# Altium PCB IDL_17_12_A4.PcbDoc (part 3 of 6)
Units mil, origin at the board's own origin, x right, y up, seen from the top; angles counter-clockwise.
Board outline 3172.06 x 10350 mil, 6 copper layers (Top Signal, Mid Signal, 3.3 Volt, GND, 5 Volt, Bot Signal), stack 122.8 mil thick; 332 components, 120 nets, 1937 pads, 197 vias.
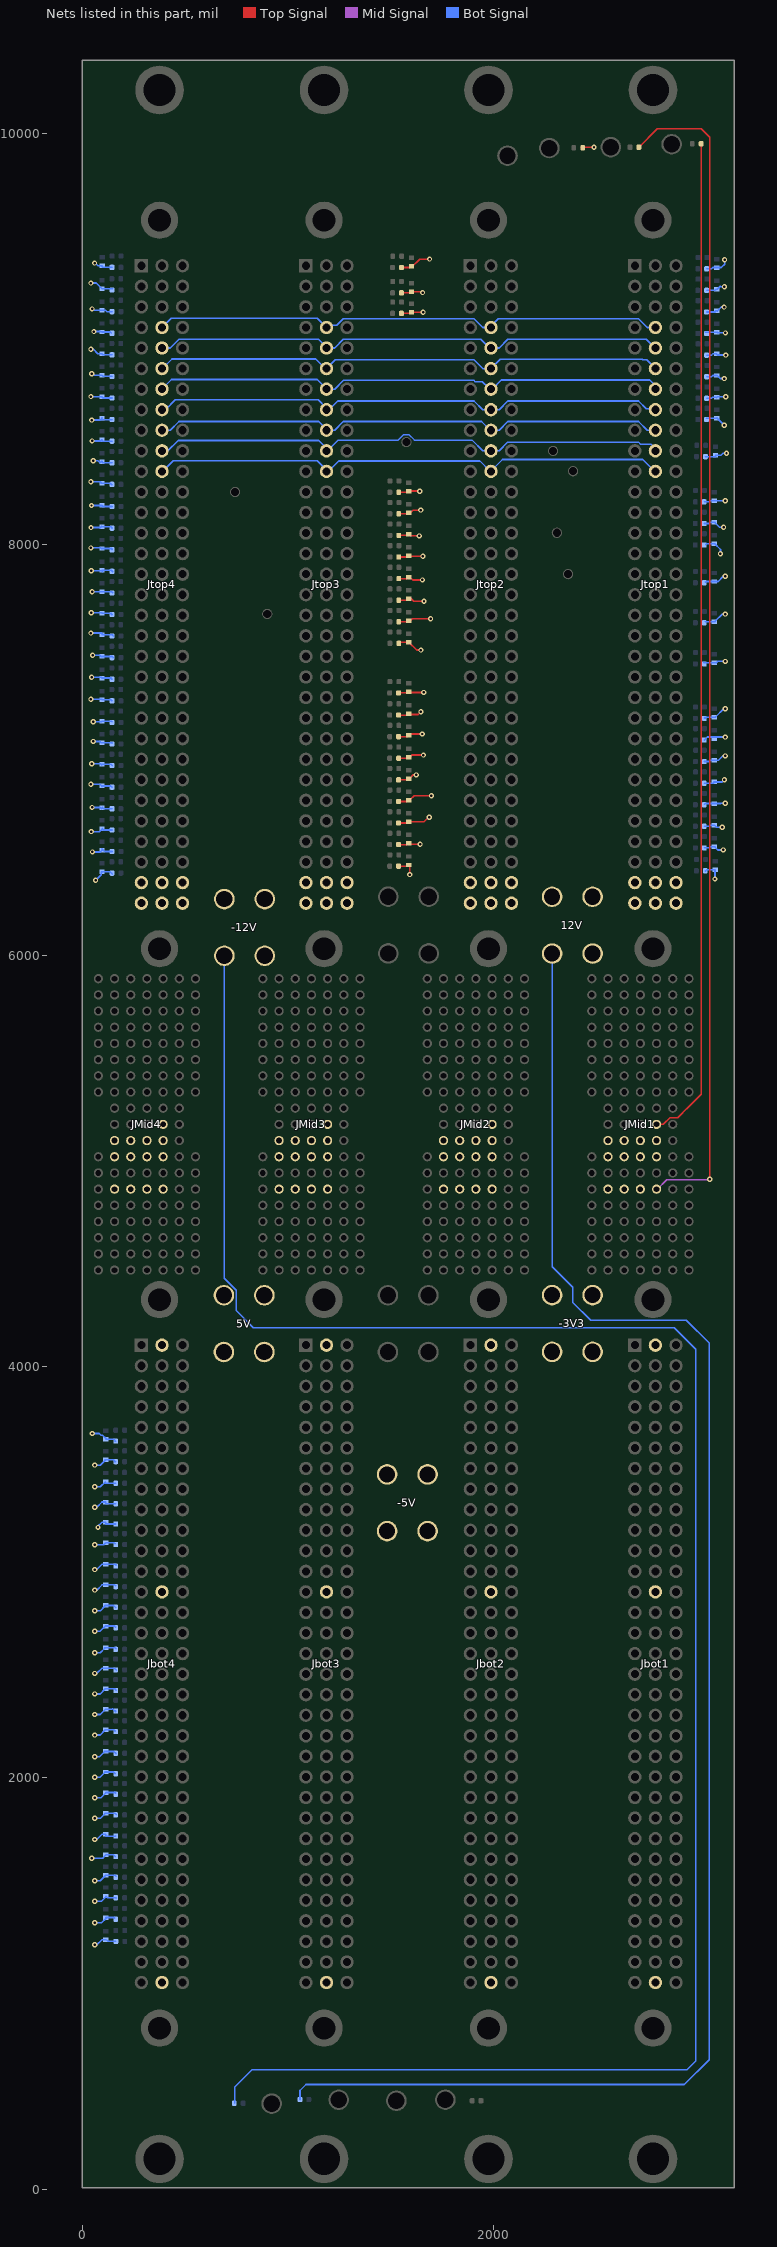
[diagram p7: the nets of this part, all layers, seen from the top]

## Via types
v1: diameter 25.59, hole 12, Top Signal to Bot Signal, 197 vias

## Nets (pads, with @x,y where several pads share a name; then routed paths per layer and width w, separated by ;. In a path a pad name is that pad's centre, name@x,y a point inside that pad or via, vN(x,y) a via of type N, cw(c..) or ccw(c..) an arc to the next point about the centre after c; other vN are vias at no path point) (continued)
5V: 5V.1@689.15,4347.73 5V.2 5V.3 5V.4 CR_IDL_17_12_TerA1.2 CR_IDL_17_12_TerA2.2 CR_IDL_17_12_TerA3.2 CR_IDL_17_12_TerA4.2 CR_IDL_17_12_TerA5.2 CR_IDL_17_12_TerA6.2 CR_IDL_17_12_TerA7.2 CR_IDL_17_12_TerA8.2 CR_IDL_17_12_TerA9.2 CR_IDL_17_12_TerA10.2 CR_IDL_17_12_TerA11.2 CR_IDL_17_12_TerA12.2 CR_IDL_17_12_TerA13.2 CR_IDL_17_12_TerA14.2 CR_IDL_17_12_TerA15.2 CR_IDL_17_12_TerA16.2 CR_IDL_17_12_TerA17.2 CR_IDL_17_12_TerA18.2 CR_IDL_17_12_TerA19.2 CR_IDL_17_12_TerA20.2 CR_IDL_17_12_TerA21.2 CR_IDL_17_12_TerA22.2 CR_IDL_17_12_TerA23.2 CR_IDL_17_12_TerA24.2 CR_IDL_17_12_TerA25.2 CR_IDL_17_12_TerA26.2 CR_IDL_17_12_TerA27.2 CR_IDL_17_12_TerA28.2 CR_IDL_17_12_TerA29.2 CR_IDL_17_12_TerA30.2 CR_IDL_17_12_TerA31.2 CR_IDL_17_12_TerA32.2 CR_IDL_17_12_TerA33.2 CR_IDL_17_12_TerA34.2 CR_IDL_17_12_TerA35.2 CR_IDL_17_12_TerA36.2 CR_IDL_17_12_TerA37.2 CR_IDL_17_12_TerA38.2 CR_IDL_17_12_TerA39.2 CR_IDL_17_12_TerA40.2 CR_IDL_17_12_TerA41.2 CR_IDL_17_12_TerA42.2 CR_IDL_17_12_TerA43.2 CR_IDL_17_12_TerA44.2 CR_IDL_17_12_TerA45.2 CR_IDL_17_12_TerA46.2 CR_IDL_17_12_TerA47.2 CR_IDL_17_12_TerA48.2 CR_IDL_17_12_TerA49.2 CR_IDL_17_12_TerA50.2 CR_IDL_17_12_TerA51.2 CR_IDL_17_12_TerA52.2 CR_IDL_17_12_TerA53.2 CR_IDL_17_12_TerA54.2 CR_IDL_17_12_TerA55.2 CR_IDL_17_12_TerA56.2 CR_IDL_17_12_TerA57.2 CR_IDL_17_12_TerA58.2 CR_IDL_17_12_TerA59.2 CR_IDL_17_12_TerA60.2 CR_IDL_17_12_TerA61.2 CR_IDL_17_12_TerA62.2 CR_IDL_17_12_TerA63.2 CR_IDL_17_12_TerA64.2 CR_IDL_17_12_TerA65.2 CR_IDL_17_12_TerA66.2 CR_IDL_17_12_TerA67.2 CR_IDL_17_12_TerA68.2 CR_IDL_17_12_TerA69.2 CR_IDL_17_12_TerA70.2 CR_IDL_17_12_TerA71.2 CR_IDL_17_12_TerA72.2 CRB_IDL_17_12_TerB1.2 CRB_IDL_17_12_TerB2.2 CRB_IDL_17_12_TerB3.2 CRB_IDL_17_12_TerB4.2 CRB_IDL_17_12_TerB5.2 CRB_IDL_17_12_TerB6.2 CRB_IDL_17_12_TerB7.2 CRB_IDL_17_12_TerB8.2 CRB_IDL_17_12_TerB9.2 CRB_IDL_17_12_TerB10.2 CRB_IDL_17_12_TerB11.2 CRB_IDL_17_12_TerB12.2 CRB_IDL_17_12_TerB13.2 CRB_IDL_17_12_TerB14.2 CRB_IDL_17_12_TerB15.2 CRB_IDL_17_12_TerB16.2 CRB_IDL_17_12_TerB17.2 CRB_IDL_17_12_TerB18.2 CRB_IDL_17_12_TerB19.2 CRB_IDL_17_12_TerB20.2 CRB_IDL_17_12_TerB21.2 CRB_IDL_17_12_TerB22.2 CRB_IDL_17_12_TerB23.2 CRB_IDL_17_12_TerB24.2 CRB_IDL_17_12_TerB25.2 Jbot1.B1 Jbot1.B13 Jbot1.B32 Jbot2.B1 Jbot2.B13 Jbot2.B32 Jbot3.B1 Jbot3.B13 Jbot3.B32 Jbot4.B1 Jbot4.B13 Jbot4.B32 Jtop1.A32 Jtop1.B31 Jtop1.B32 Jtop1.C32 Jtop2.A32 Jtop2.B31 Jtop2.B32 Jtop2.C32 Jtop3.A32 Jtop3.B31 Jtop3.B32 Jtop3.C32 Jtop4.A32 Jtop4.B31 Jtop4.B32 Jtop4.C32 R1R_IDL_17_12_TerA1.2 R1R_IDL_17_12_TerA2.2 R1R_IDL_17_12_TerA3.2 R1R_IDL_17_12_TerA4.2 R1R_IDL_17_12_TerA5.2 R1R_IDL_17_12_TerA6.2 R1R_IDL_17_12_TerA7.2 R1R_IDL_17_12_TerA8.2 R1R_IDL_17_12_TerA9.2 R1R_IDL_17_12_TerA10.2 R1R_IDL_17_12_TerA11.2 R1R_IDL_17_12_TerA12.2 R1R_IDL_17_12_TerA13.2 R1R_IDL_17_12_TerA14.2 R1R_IDL_17_12_TerA15.2 R1R_IDL_17_12_TerA16.2 R1R_IDL_17_12_TerA17.2 R1R_IDL_17_12_TerA18.2 R1R_IDL_17_12_TerA19.2 R1R_IDL_17_12_TerA20.2 R1R_IDL_17_12_TerA21.2 R1R_IDL_17_12_TerA22.2 R1R_IDL_17_12_TerA23.2 R1R_IDL_17_12_TerA24.2 R1R_IDL_17_12_TerA25.2 R1R_IDL_17_12_TerA26.2 R1R_IDL_17_12_TerA27.2 R1R_IDL_17_12_TerA28.2 R1R_IDL_17_12_TerA29.2 R1R_IDL_17_12_TerA30.2 R1R_IDL_17_12_TerA31.2 R1R_IDL_17_12_TerA32.2 R1R_IDL_17_12_TerA33.2 R1R_IDL_17_12_TerA34.2 R1R_IDL_17_12_TerA35.2 R1R_IDL_17_12_TerA36.2 R1R_IDL_17_12_TerA37.2 R1R_IDL_17_12_TerA38.2 R1R_IDL_17_12_TerA39.2 R1R_IDL_17_12_TerA40.2 R1R_IDL_17_12_TerA41.2 R1R_IDL_17_12_TerA42.2 R1R_IDL_17_12_TerA43.2 R1R_IDL_17_12_TerA44.2 R1R_IDL_17_12_TerA45.2 R1R_IDL_17_12_TerA46.2 R1R_IDL_17_12_TerA47.2 R1R_IDL_17_12_TerA48.2 R1R_IDL_17_12_TerA49.2 R1R_IDL_17_12_TerA50.2 R1R_IDL_17_12_TerA51.2 R1R_IDL_17_12_TerA52.2 R1R_IDL_17_12_TerA53.2 R1R_IDL_17_12_TerA54.2 R1R_IDL_17_12_TerA55.2 R1R_IDL_17_12_TerA56.2 R1R_IDL_17_12_TerA57.2 R1R_IDL_17_12_TerA58.2 R1R_IDL_17_12_TerA59.2 R1R_IDL_17_12_TerA60.2 R1R_IDL_17_12_TerA61.2 R1R_IDL_17_12_TerA62.2 R1R_IDL_17_12_TerA63.2 R1R_IDL_17_12_TerA64.2 R1R_IDL_17_12_TerA65.2 R1R_IDL_17_12_TerA66.2 R1R_IDL_17_12_TerA67.2 R1R_IDL_17_12_TerA68.2 R1R_IDL_17_12_TerA69.2 R1R_IDL_17_12_TerA70.2 R1R_IDL_17_12_TerA71.2 R1R_IDL_17_12_TerA72.2 R1RB_IDL_17_12_TerB1.2 R1RB_IDL_17_12_TerB2.2 R1RB_IDL_17_12_TerB3.2 R1RB_IDL_17_12_TerB4.2 R1RB_IDL_17_12_TerB5.2 R1RB_IDL_17_12_TerB6.2 R1RB_IDL_17_12_TerB7.2 R1RB_IDL_17_12_TerB8.2 R1RB_IDL_17_12_TerB9.2 R1RB_IDL_17_12_TerB10.2 R1RB_IDL_17_12_TerB11.2 R1RB_IDL_17_12_TerB12.2 R1RB_IDL_17_12_TerB13.2 R1RB_IDL_17_12_TerB14.2 R1RB_IDL_17_12_TerB15.2 R1RB_IDL_17_12_TerB16.2 R1RB_IDL_17_12_TerB17.2 R1RB_IDL_17_12_TerB18.2 R1RB_IDL_17_12_TerB19.2 R1RB_IDL_17_12_TerB20.2 R1RB_IDL_17_12_TerB21.2 R1RB_IDL_17_12_TerB22.2 R1RB_IDL_17_12_TerB23.2 R1RB_IDL_17_12_TerB24.2 R1RB_IDL_17_12_TerB25.2 R5.2 | length 10859.5
  Top Signal w8: R1R_IDL_17_12_TerA24.2@1538.9,6434.64 1583.44,6434.64 1588.6,6439.8 CR_IDL_17_12_TerA24.2@1592.4,6443.59 ; R1R_IDL_17_12_TerA25.2@1538.9,6539.64 1579.21,6539.64 CR_IDL_17_12_TerA25.2@1586.42,6546.84 ; R1R_IDL_17_12_TerA26.2@1538.9,6644.64 1580.88,6644.64 CR_IDL_17_12_TerA26.2@1587.32,6651.08 ; R1R_IDL_17_12_TerA27.2@1538.9,6749.64 1577.14,6749.64 1585.45,6757.95 CR_IDL_17_12_TerA27.2@1586.49,6758.99 ; R1R_IDL_17_12_TerA28.2@1538.9,6854.64 1577.83,6854.64 CR_IDL_17_12_TerA28.2@1585.51,6862.31 ; R1R_IDL_17_12_TerA29.2@1538.9,6959.64 1579.01,6959.64 CR_IDL_17_12_TerA29.2@1584.53,6965.15 ; R1R_IDL_17_12_TerA30.2@1538.9,7064.64 1581.18,7064.64 CR_IDL_17_12_TerA30.2@1582.86,7066.32 ; R1R_IDL_17_12_TerA31.2@1538.9,7169.64 1584.33,7169.64 CR_IDL_17_12_TerA31.2@1588.95,7174.26 ; R1R_IDL_17_12_TerA32.2@1538.9,7277.64 1577.03,7277.64 1585.4,7286.01 CR_IDL_17_12_TerA32.2@1585.98,7286.59 ; R1R_IDL_17_12_TerA33.2@1539.86,7518.53 1545.3,7523.98 CR_IDL_17_12_TerA33.2@1588.79,7523.98 ; R1R_IDL_17_12_TerA34.2@1539.86,7623.53 1582.98,7623.53 1588.85,7629.4 CR_IDL_17_12_TerA34.2@1592.32,7632.87 ; R1R_IDL_17_12_TerA35.2@1539.86,7728.53 1579.98,7728.53 1587.35,7735.9 CR_IDL_17_12_TerA35.2@1587.85,7736.4 ; R1R_IDL_17_12_TerA36.2@1539.86,7833.53 1581.44,7833.53 CR_IDL_17_12_TerA36.2@1587.85,7839.94 ; R1R_IDL_17_12_TerA37.2@1539.86,7938.53 1585.58,7938.53 CR_IDL_17_12_TerA37.2@1587.85,7940.8 ; R1R_IDL_17_12_TerA38.2@1539.86,8043.53 1580.8,8043.53 CR_IDL_17_12_TerA38.2@1586.07,8048.8 ; R1R_IDL_17_12_TerA39.2@1539.86,8148.53 1587.62,8148.53 1591.17,8152.08 CR_IDL_17_12_TerA39.2@1592.32,8153.23 ; R1R_IDL_17_12_TerA40.2@1539.86,8253.53 1588.19,8253.53 1591.45,8256.8 CR_IDL_17_12_TerA40.2@1593.21,8258.55 ; R1R_IDL_17_12_TerA43.2@1552.83,9346.47 1593.74,9346.47 CR_IDL_17_12_TerA43.2@1600.3,9353.03 ; R1R_IDL_17_12_TerA41.2@1552.9,9123.5 1599.94,9123.5 CR_IDL_17_12_TerA41.2@1603.07,9126.63 ; R1R_IDL_17_12_TerA42.2@1552.9,9223.5 1594.16,9223.5 1600.96,9230.3 CR_IDL_17_12_TerA42.2@1601.38,9230.72 ; CR_IDL_17_12_TerA30.2@1582.88,7066.3 1587.49,7070.91 1594.14,7077.56 v1(1654.34,7077.56) ; CR_IDL_17_12_TerA29.2@1587.18,6962.58 CR_IDL_17_12_TerA29.2@1589,6964.4 ; CR_IDL_17_12_TerA26.2@1587.86,6650.54 1662.88,6650.54 v1@1686.23,6673.9 ; CR_IDL_17_12_TerA33.2@1588.79,7524.33 1627.16,7485.96 v1(1647.64,7485.96) ; CR_IDL_17_12_TerA40.2@1588.81,8259.44 1642.33,8259.44 1643.18,8259.44 v1@1645.87,8262.12 ; CR_IDL_17_12_TerA29.2@1589.52,6960.85 1591.04,6962.36 1604.9,6976.22 1605.75,6975.36 v1(1659.66,6975.36) ; CR_IDL_17_12_TerA25.2@1589.84,6543.42 1592.23,6541.03 v1(1643.44,6541.03) ; CR_IDL_17_12_TerA24.2@1590.64,6439.47 1592.97,6437.14 v1(1592.97,6394.12) ; CR_IDL_17_12_TerA31.2@1591.1,7172.76 1635.32,7172.76 v1(1647.85,7185.29) ; CR_IDL_17_12_TerA38.2@1591.81,8044.65 1595.25,8041.21 v1(1639.76,8041.21) ; CR_IDL_17_12_TerA32.2@1593.84,7281.96 1596.18,7279.61 v1(1660.76,7279.61) ; CR_IDL_17_12_TerA28.2@1594.23,6862.39 1610.57,6878.73 v1(1625.38,6878.73) ; CR_IDL_17_12_TerA37.2@1594.89,7943.26 1595.47,7942.68 v1(1657.31,7942.68) ; CR_IDL_17_12_TerA39.2@1595.28,8152.99 1608.95,8166.66 v1(1647.17,8166.66) ; CR_IDL_17_12_TerA27.2@1595.79,6759.06 1614.62,6777.88 v1(1698.8,6777.88) ; CR_IDL_17_12_TerA35.2@1596.63,7739.75 1612.9,7723.48 v1(1662.58,7723.48) ; CR_IDL_17_12_TerA36.2@1596.97,7837.36 1607.52,7826.81 v1(1655.14,7826.81) ; CR_IDL_17_12_TerA34.2@1598.09,7630.59 1605.85,7638.35 1606.62,7637.58 v1(1694.69,7637.58) ; CR_IDL_17_12_TerA41.2@1601.86,9129.41 v1(1658.08,9129.39) 1658.31,9129.41 v1@1658.71,9129.81 ; CR_IDL_17_12_TerA42.2@1601.86,9229.41 1651.8,9229.41 v1@1655.52,9225.69 ; CR_IDL_17_12_TerA43.2@1604.05,9349.28 1604.46,9349.7 1642.18,9387.42 v1(1689.41,9387.42) ; v1@1686.23,6672.65 v1(1687.49,6672.65) ; R5.2@2427.91,9929.8 2428.82,9930.71 2434.51,9930.71 v1@2484.35,9930.71
  Bot Signal w8: v1@41.67,9270.96 42.59,9270.96 68.02,9270.96 CR_IDL_17_12_TerA71.2@96.11,9242.87 145.07,9242.87 147.59,9242.87 R1R_IDL_17_12_TerA71.2@147.8,9243.08 ; v1(42.59,6832.73) 86.8,6832.73 CR_IDL_17_12_TerA48.2@94.66,6824.87 ; v1(42.59,7246.73) CR_IDL_17_12_TerA52.2@96.11,7246.73 ; v1(42.59,7568.73) 95.01,7568.73 99.99,7563.76 CR_IDL_17_12_TerA55.2@100.42,7563.32 ; v1(42.59,7982.73) 89.51,7982.73 CR_IDL_17_12_TerA59.2@92.37,7979.87 ; v1(42.59,8304.73) 87.39,8304.73 CR_IDL_17_12_TerA62.2@91.26,8300.86 ; v1(42.59,8718.73) 64.68,8718.73 65.53,8717.87 CR_IDL_17_12_TerA66.2@96.11,8717.87 ; v1(42.59,8948.73) 54.68,8948.73 75.53,8927.87 CR_IDL_17_12_TerA68.2@96.11,8927.87 ; v1(42.87,8081.94) 89.32,8081.94 CR_IDL_17_12_TerA60.2@92.25,8084.87 ; v1(43.55,7667.69) 95.54,7667.69 97.23,7666 CR_IDL_17_12_TerA56.2@98.36,7664.87 ; v1(43.88,7871.42) 95.89,7871.42 CR_IDL_17_12_TerA58.2@99.07,7868.25 ; v1(44.02,6602.94) 83.46,6602.94 84.59,6601.81 97.88,6615.1 CR_IDL_17_12_TerA46.2@98.23,6615.45 ; v1(45.27,8189.08) 87.92,8189.08 CR_IDL_17_12_TerA61.2@90.58,8186.43 ; v1(45.52,7353.76) 93.68,7353.76 CR_IDL_17_12_TerA53.2@96.84,7350.6 ; v1(45.96,8604.68) 87.42,8604.68 CR_IDL_17_12_TerA65.2@91.42,8608.68 ; v1(46.66,8829.91) 46.66,8834.92 49.17,8832.41 58.71,8822.87 CR_IDL_17_12_TerA67.2@96.11,8822.87 CR_IDL_17_12_TerA67.2@98.39,8822.87 ; v1(46.72,1609.92) 100.27,1609.92 CRB_IDL_17_12_TerB5.2@111.44,1621.09 ; v1(47.01,6933.26) 89.04,6933.26 CR_IDL_17_12_TerA49.2@92.42,6929.87 ; v1(47.86,7769.72) CR_IDL_17_12_TerA57.2@91.74,7769.72 ; v1(48.05,8502.87) 88.84,8502.87 CR_IDL_17_12_TerA64.2@92.44,8506.47 ; v1(48.05,9145.09) 48.05,9148.53 49.77,9146.81 58.71,9137.87 CR_IDL_17_12_TerA70.2@96.11,9137.87 115.37,9137.87 121.28,9131.97 R1R_IDL_17_12_TerA70.2@145.07,9131.97 ; v1(48.19,6720.46) 88.75,6720.46 92.72,6716.49 CR_IDL_17_12_TerA47.2@94.44,6714.77 ; v1(48.7,3675.32) 83.78,3675.32 91.65,3667.45 99.25,3667.45 117.1,3649.6 CRB_IDL_17_12_TerB25.2@118.61,3648.09 ; v1(49.73,6503.82) 87.85,6503.82 CR_IDL_17_12_TerA45.2@94.24,6510.21 ; v1(50.5,7461.27) 86.36,7461.27 CR_IDL_17_12_TerA54.2@90.46,7457.17 ; v1(53.84,8406.95) 77.41,8406.95 86.78,8397.58 CR_IDL_17_12_TerA63.2@92.07,8402.87 ; v1(54.26,7041.27) 86.39,7041.27 CR_IDL_17_12_TerA50.2@92.53,7035.14 ; v1@54.48,7136.82 93.05,7136.82 CR_IDL_17_12_TerA51.2@96.11,7139.87 142.53,7139.87 R1R_IDL_17_12_TerA51.2@145.25,7137.16 ; v1(57.32,9035.23) 91.07,9035.23 CR_IDL_17_12_TerA69.2@91.56,9034.74 ; v1(60.92,1295.61) 93.84,1295.61 CRB_IDL_17_12_TerB2.2@116.46,1318.22 ; v1(60.92,1400.61) 93.76,1400.61 CRB_IDL_17_12_TerB3.2@114.45,1421.3 ; v1(60.92,1500.61) 88.34,1500.61 CRB_IDL_17_12_TerB4.2@112.78,1525.05 ; v1(60.92,1700.61) 70.78,1700.61 96.11,1725.94 CRB_IDL_17_12_TerB6.2@114.44,1725.94 114.44,1717.03 163.26,1717.03 R1RB_IDL_17_12_TerB6.2@163.26,1717.44 ; v1(60.92,1803.61) 89.14,1803.61 CRB_IDL_17_12_TerB7.2@111.1,1825.57 ; v1(60.92,1903.61) 91.18,1903.61 115.48,1927.91 CRB_IDL_17_12_TerB8.2@116.51,1928.94 ; v1(60.92,2003.61) 86.88,2003.61 CRB_IDL_17_12_TerB9.2@110.86,2027.59 ; v1(60.92,2103.61) 84.62,2103.61 CRB_IDL_17_12_TerB10.2@108.68,2127.67 ; v1(60.92,2208.61) 87.46,2208.61 CRB_IDL_17_12_TerB11.2@110.49,2231.64 ; v1(60.92,2308.61) 88.57,2308.61 CRB_IDL_17_12_TerB12.2@112.66,2332.7 ; v1(60.92,2408.61) 87.5,2408.61 CRB_IDL_17_12_TerB13.2@112.66,2433.77 ; v1(60.92,2508.61) 70.78,2508.61 96.11,2533.94 CRB_IDL_17_12_TerB14.2@114.44,2533.94 156.67,2533.94 164.22,2526.39 R1RB_IDL_17_12_TerB14.2@165.91,2524.7 ; v1(60.92,2608.61) 87.54,2608.61 CRB_IDL_17_12_TerB15.2@108.31,2629.39 ; v1(60.92,2713.61) 86.96,2713.61 CRB_IDL_17_12_TerB16.2@111.6,2738.25 ; v1(60.92,2813.61) 89.04,2813.61 CRB_IDL_17_12_TerB17.2@110.1,2834.67 ; v1(60.92,2913.61) 70.78,2913.61 96.11,2938.94 CRB_IDL_17_12_TerB18.2@114.44,2938.94 158.66,2938.94 R1RB_IDL_17_12_TerB18.2@163.33,2934.26 ; v1(60.92,3013.61) 70.78,3013.61 96.11,3038.94 CRB_IDL_17_12_TerB19.2@114.44,3038.94 160.71,3038.94 R1RB_IDL_17_12_TerB19.2@165.59,3034.06 ; v1(60.92,3134.61) 105.49,3134.61 CRB_IDL_17_12_TerB20.2@111.82,3140.94 ; v1(60.92,3316.61) 70.78,3316.61 96.11,3341.94 CRB_IDL_17_12_TerB22.2@114.44,3341.94 114.44,3333.03 163.26,3333.03 R1RB_IDL_17_12_TerB22.2@163.26,3333.44 ; v1(60.92,3416.61) 88.42,3416.61 CRB_IDL_17_12_TerB23.2@111.5,3439.69 ; v1(60.92,3521.61) 87.78,3521.61 CRB_IDL_17_12_TerB24.2@111.93,3545.76 ; v1(61.62,1188.14) 71.47,1188.14 96.8,1213.47 CRB_IDL_17_12_TerB1.2@115.14,1213.47 ; v1@62.22,9369.75 76.63,9355.34 CR_IDL_17_12_TerA72.2@97.42,9355.34 ; v1(65.37,6365.68) 89.73,6390.05 92.13,6390.05 CR_IDL_17_12_TerA44.2@92.13,6403.15 ; 76.53,8189.87 CR_IDL_17_12_TerA61.2@96.11,8189.87 ; v1(76.92,3218.61) 70.78,3218.61 73.85,3221.68 96.11,3243.94 CRB_IDL_17_12_TerB21.2@114.44,3243.94 114.44,3235.03 163.26,3235.03 R1RB_IDL_17_12_TerB21.2@163.26,3235.44 ; CR_IDL_17_12_TerA54.2@90.46,7454.87 CR_IDL_17_12_TerA54.2@96.11,7454.87 145.03,7454.87 148,7451.9 R1R_IDL_17_12_TerA54.2@151.36,7448.55 ; CR_IDL_17_12_TerA62.2@91.26,8297.87 CR_IDL_17_12_TerA62.2@96.11,8297.87 136.35,8297.87 143.66,8290.56 R1R_IDL_17_12_TerA62.2@144.91,8289.32 ; CR_IDL_17_12_TerA57.2@92.07,7769.87 CR_IDL_17_12_TerA57.2@96.11,7769.87 143.11,7769.87 147.04,7765.94 R1R_IDL_17_12_TerA57.2@148.3,7764.68 ; CR_IDL_17_12_TerA57.2@92.07,7770.04 CR_IDL_17_12_TerA57.2@91.74,7769.72 ; CR_IDL_17_12_TerA44.2@92.13,6406.56 CR_IDL_17_12_TerA44.2@92.13,6403.15 ; CR_IDL_17_12_TerA57.2@93.29,7769.44 93.01,7769.72 CR_IDL_17_12_TerA57.2@91.74,7769.72 ; CR_IDL_17_12_TerA72.2@93.55,9354.51 95.07,9352.99 100.54,9347.52 R1R_IDL_17_12_TerA72.2@145.05,9347.52 ; CR_IDL_17_12_TerA64.2@93.85,8507.87 CR_IDL_17_12_TerA64.2@96.11,8507.87 ; CR_IDL_17_12_TerA64.2@93.97,8504.94 96.95,8501.97 R1R_IDL_17_12_TerA64.2@145.07,8501.97 ; CR_IDL_17_12_TerA59.2@94.31,7977.93 94.24,7978.01 CR_IDL_17_12_TerA59.2@92.37,7979.87 ; CR_IDL_17_12_TerA63.2@94.31,8405.11 94.09,8404.89 CR_IDL_17_12_TerA63.2@92.07,8402.87 ; CR_IDL_17_12_TerA44.2@94.57,6405.59 CR_IDL_17_12_TerA44.2@92.13,6403.15 ; CR_IDL_17_12_TerA60.2@94.65,8087.27 94.18,8086.8 CR_IDL_17_12_TerA60.2@92.25,8084.87 ; CR_IDL_17_12_TerA45.2@94.71,6519.95 99.44,6515.21 108.69,6505.97 R1R_IDL_17_12_TerA45.2@145.07,6505.97 ; CR_IDL_17_12_TerA49.2@95.33,6926.97 94.26,6928.03 CR_IDL_17_12_TerA49.2@92.42,6929.87 ; CR_IDL_17_12_TerA61.2@95.33,8186.77 98.13,8183.97 R1R_IDL_17_12_TerA61.2@145.07,8183.97 ; CR_IDL_17_12_TerA44.2@95.41,6406.87 CR_IDL_17_12_TerA44.2@96.11,6406.87 136.8,6406.87 143.89,6399.79 R1R_IDL_17_12_TerA44.2@146.94,6396.74 ; CR_IDL_17_12_TerA50.2@96.11,7034.87 145.07,7034.87 145.32,7034.87 R1R_IDL_17_12_TerA50.2@146.94,7033.25 ; CR_IDL_17_12_TerA52.2@96.11,7244.87 139.06,7244.87 R1R_IDL_17_12_TerA52.2@140.83,7243.11 ; CR_IDL_17_12_TerA53.2@96.11,7349.87 140.69,7349.87 R1R_IDL_17_12_TerA53.2@142.53,7348.03 ; CR_IDL_17_12_TerA55.2@96.11,7559.87 145.07,7559.87 145.98,7559.87 148.47,7557.38 R1R_IDL_17_12_TerA55.2@151.36,7554.49 ; CR_IDL_17_12_TerA56.2@96.11,7664.87 CR_IDL_17_12_TerA56.2@98.36,7664.87 ; CR_IDL_17_12_TerA58.2@96.11,7874.87 140.66,7874.87 145.82,7869.72 R1R_IDL_17_12_TerA58.2@148.3,7867.23 ; CR_IDL_17_12_TerA63.2@96.11,8402.87 CR_IDL_17_12_TerA63.2@92.07,8402.87 ; CR_IDL_17_12_TerA69.2@96.11,9032.87 136.49,9032.87 R1R_IDL_17_12_TerA69.2@141.35,9028.02 ; CR_IDL_17_12_TerA46.2@97.21,6617.98 CR_IDL_17_12_TerA46.2@100.13,6615.07 ; CR_IDL_17_12_TerA63.2@97.37,8399.68 100.08,8396.97 R1R_IDL_17_12_TerA63.2@145.07,8396.97 ; CR_IDL_17_12_TerA65.2@98.05,8615.3 95.86,8613.12 CR_IDL_17_12_TerA65.2@91.42,8608.68 ; CR_IDL_17_12_TerA48.2@98.23,6821.3 95.38,6824.15 CR_IDL_17_12_TerA48.2@94.66,6824.87 ; CR_IDL_17_12_TerA66.2@98.39,8713.44 99.86,8711.97 R1R_IDL_17_12_TerA66.2@145.07,8711.97 ; CR_IDL_17_12_TerA67.2@98.39,8821.08 102.5,8816.97 R1R_IDL_17_12_TerA67.2@145.07,8816.97 ; CR_IDL_17_12_TerA68.2@98.61,8923.78 100.42,8921.97 R1R_IDL_17_12_TerA68.2@145.07,8921.97 ; CR_IDL_17_12_TerA47.2@98.73,6720.15 104.91,6713.97 R1R_IDL_17_12_TerA47.2@145.07,6713.97 ; CR_IDL_17_12_TerA46.2@100.13,6610.97 R1R_IDL_17_12_TerA46.2@145.07,6610.97 ; CRB_IDL_17_12_TerB15.2@108.31,2633.94 CRB_IDL_17_12_TerB15.2@114.44,2633.94 158.1,2633.94 R1RB_IDL_17_12_TerB15.2@164.46,2627.58 ; CRB_IDL_17_12_TerB10.2@108.68,2128.94 CRB_IDL_17_12_TerB10.2@114.44,2128.94 153.77,2128.94 162.77,2119.95 R1RB_IDL_17_12_TerB10.2@164.46,2118.25 ; CRB_IDL_17_12_TerB17.2@110.1,2838.94 CRB_IDL_17_12_TerB17.2@114.44,2838.94 152.79,2838.94 162.28,2829.45 R1RB_IDL_17_12_TerB17.2@162.56,2829.17 ; CRB_IDL_17_12_TerB11.2@110.49,2233.94 CRB_IDL_17_12_TerB11.2@114.44,2233.94 154.91,2233.94 R1RB_IDL_17_12_TerB11.2@161.2,2227.65 ; CRB_IDL_17_12_TerB9.2@110.86,2028.94 CRB_IDL_17_12_TerB9.2@114.44,2028.94 153.09,2028.94 R1RB_IDL_17_12_TerB9.2@160.87,2021.16 ; CRB_IDL_17_12_TerB7.2@111.1,1828.94 CRB_IDL_17_12_TerB7.2@114.44,1828.94 158.6,1828.94 165.18,1822.36 R1RB_IDL_17_12_TerB7.2@165.32,1822.22 ; CRB_IDL_17_12_TerB24.2@111.24,3546.94 CRB_IDL_17_12_TerB24.2@114.44,3546.94 153.78,3546.94 R1RB_IDL_17_12_TerB24.2@157.42,3543.31 ; CRB_IDL_17_12_TerB23.2@111.5,3436.15 114.22,3433.44 114.44,3433.44 R1RB_IDL_17_12_TerB23.2@163.26,3433.44 ; CRB_IDL_17_12_TerB16.2@111.6,2738.94 CRB_IDL_17_12_TerB16.2@114.44,2738.94 156.87,2738.94 R1RB_IDL_17_12_TerB16.2@163.06,2732.75 ; CRB_IDL_17_12_TerB12.2@112.66,2333.94 CRB_IDL_17_12_TerB12.2@114.44,2333.94 143.6,2333.94 147.07,2337.42 R1RB_IDL_17_12_TerB12.2@159.05,2325.44 ; CRB_IDL_17_12_TerB13.2@112.66,2433.94 CRB_IDL_17_12_TerB13.2@114.44,2433.94 158.13,2433.94 164.95,2427.13 R1RB_IDL_17_12_TerB13.2@165.19,2426.89 ; CRB_IDL_17_12_TerB4.2@112.78,1525.94 CRB_IDL_17_12_TerB4.2@114.44,1525.94 160.07,1525.94 R1RB_IDL_17_12_TerB4.2@164.32,1521.7 ; CRB_IDL_17_12_TerB2.2@114.44,1320.94 155.24,1320.94 R1RB_IDL_17_12_TerB2.2@157.29,1318.89 ; CRB_IDL_17_12_TerB5.2@114.44,1625.94 152.44,1625.94 R1RB_IDL_17_12_TerB5.2@160.63,1617.75 ; CRB_IDL_17_12_TerB8.2@114.44,1928.94 CRB_IDL_17_12_TerB8.2@116.51,1928.94 ; CRB_IDL_17_12_TerB20.2@114.44,3143.94 155.18,3143.94 R1RB_IDL_17_12_TerB20.2@160.44,3138.69 ; CRB_IDL_17_12_TerB25.2@114.44,3646.94 155.15,3646.94 R1RB_IDL_17_12_TerB25.2@159.24,3642.85 ; CRB_IDL_17_12_TerB3.2@116.14,1424.77 123.48,1417.44 R1RB_IDL_17_12_TerB3.2@163.16,1417.44 ; CRB_IDL_17_12_TerB1.2@118.73,1213.31 127.08,1204.96 R1RB_IDL_17_12_TerB1.2@163.95,1204.96 ; R1R_IDL_17_12_TerA52.2@140.83,7238.97 R1R_IDL_17_12_TerA52.2@145.07,7238.97 ; R1R_IDL_17_12_TerA56.2@141.85,7658.97 R1R_IDL_17_12_TerA56.2@145.07,7658.97 ; R1R_IDL_17_12_TerA56.2@141.85,7664.51 141.49,7664.87 CR_IDL_17_12_TerA56.2@98.36,7664.87 ; R1R_IDL_17_12_TerA53.2@142.53,7343.97 R1R_IDL_17_12_TerA53.2@145.07,7343.97 ; R1R_IDL_17_12_TerA59.2@144.91,7973.97 R1R_IDL_17_12_TerA59.2@145.07,7973.97 ; R1R_IDL_17_12_TerA59.2@144.91,7977.25 142.29,7979.87 CR_IDL_17_12_TerA59.2@96.11,7979.87 CR_IDL_17_12_TerA59.2@92.37,7979.87 ; R1R_IDL_17_12_TerA60.2@144.91,8078.97 R1R_IDL_17_12_TerA60.2@145.07,8078.97 ; R1R_IDL_17_12_TerA60.2@144.91,8081.5 141.53,8084.87 CR_IDL_17_12_TerA60.2@96.11,8084.87 CR_IDL_17_12_TerA60.2@92.25,8084.87 ; R1R_IDL_17_12_TerA65.2@145.07,8606.97 96.11,8606.97 93.14,8606.97 91.67,8608.44 CR_IDL_17_12_TerA65.2@91.42,8608.68 ; R1R_IDL_17_12_TerA49.2@145.59,6924.25 145.47,6924.37 139.96,6929.87 CR_IDL_17_12_TerA49.2@96.11,6929.87 CR_IDL_17_12_TerA49.2@92.42,6929.87 ; R1R_IDL_17_12_TerA48.2@146,6818.65 145.37,6819.27 139.77,6824.87 CR_IDL_17_12_TerA48.2@96.11,6824.87 CR_IDL_17_12_TerA48.2@94.66,6824.87 ; R1RB_IDL_17_12_TerB24.2@157.42,3538.44 R1RB_IDL_17_12_TerB24.2@163.26,3538.44 ; R1RB_IDL_17_12_TerB25.2@159.24,3638.44 R1RB_IDL_17_12_TerB25.2@163.26,3638.44 ; R1RB_IDL_17_12_TerB12.2@161.93,2322.56 161.15,2323.33 R1RB_IDL_17_12_TerB12.2@159.05,2325.44 ; R1RB_IDL_17_12_TerB3.2@163.26,1417.44 R1RB_IDL_17_12_TerB3.2@163.16,1417.44 ; R1RB_IDL_17_12_TerB12.2@163.26,2325.44 R1RB_IDL_17_12_TerB12.2@159.05,2325.44 ; R1RB_IDL_17_12_TerB8.2@163.37,1926.15 160.58,1928.94 CRB_IDL_17_12_TerB8.2@116.51,1928.94 ; R1RB_IDL_17_12_TerB3.2@164.65,1415.95 163.21,1417.39 R1RB_IDL_17_12_TerB3.2@163.16,1417.44 ; R1R_IDL_17_12_TerA9.2@3022.85,7426.41 3024.82,7424.44 3025.76,7424.44 CR_IDL_17_12_TerA9.2@3074.72,7424.44 CR_IDL_17_12_TerA9.2@3085.45,7424.44 ; R1R_IDL_17_12_TerA13.2@3025.39,8101.75 3049.28,8101.75 3055.19,8107.66 CR_IDL_17_12_TerA13.2@3074.35,8107.66 CR_IDL_17_12_TerA13.2@3079.65,8107.66 ; R1R_IDL_17_12_TerA14.2@3025.39,8206.75 3049.28,8206.75 3055.19,8212.66 CR_IDL_17_12_TerA14.2@3074.35,8212.66 3105.32,8212.66 3105.39,8212.73 v1(3127.87,8212.73) ; R1R_IDL_17_12_TerA2.2@3025.76,6523.54 3049.28,6523.54 3055.19,6529.44 CR_IDL_17_12_TerA2.2@3074.72,6529.44 CR_IDL_17_12_TerA2.2@3079.65,6529.44 ; R1R_IDL_17_12_TerA3.2@3025.76,6628.54 3049.28,6628.54 3055.19,6634.44 CR_IDL_17_12_TerA3.2@3074.72,6634.44 ; R1R_IDL_17_12_TerA5.2@3025.76,6838.54 3069.6,6838.54 CR_IDL_17_12_TerA5.2@3072.26,6841.2 ; R1R_IDL_17_12_TerA6.2@3025.76,6943.54 3049.28,6943.54 3055.19,6949.44 CR_IDL_17_12_TerA6.2@3074.72,6949.44 3095.08,6949.44 3116.37,6970.73 v1(3128.24,6970.73) ; R1R_IDL_17_12_TerA7.2@3025.76,7048.54 3028.66,7048.54 3028.66,7049.99 3041.4,7062.73 3074.72,7062.73 v1(3128.24,7062.73) ; R1R_IDL_17_12_TerA4.2@3026.24,6735.1 3030.58,6739.44 CR_IDL_17_12_TerA4.2@3074.72,6739.44 3105.08,6739.44 3106.37,6740.73 v1(3128.24,6740.73) ; R1R_IDL_17_12_TerA10.2@3030,7624.44 CR_IDL_17_12_TerA10.2@3074.72,7624.44 CR_IDL_17_12_TerA10.2@3078.3,7624.44 ; R1R_IDL_17_12_TerA20.2@3030.05,9031.3 3037.1,9031.3 CR_IDL_17_12_TerA20.2@3086.06,9031.3 ; R1R_IDL_17_12_TerA1.2@3030.73,6409.91 3031.94,6411.12 3039.03,6418.21 CR_IDL_17_12_TerA1.2@3079.72,6418.21 ; R1R_IDL_17_12_TerA11.2@3031.08,7815.91 3034.62,7819.44 CR_IDL_17_12_TerA11.2@3074.72,7819.44 3093.08,7819.44 3118.37,7844.73 v1(3128.24,7844.73) ; R1R_IDL_17_12_TerA15.2@3031.4,8426.69 3079.29,8426.69 CR_IDL_17_12_TerA15.2@3081.63,8429.03 ; R1R_IDL_17_12_TerA8.2@3032.89,7153.54 R1R_IDL_17_12_TerA8.2@3025.76,7153.54 3030.73,7158.51 CR_IDL_17_12_TerA8.2@3073.72,7158.51 ; R1R_IDL_17_12_TerA12.2@3033.02,7999.03 3036.65,8002.66 CR_IDL_17_12_TerA12.2@3074.35,8002.66 CR_IDL_17_12_TerA12.2@3076.75,8002.66 ; R1R_IDL_17_12_TerA16.2@3034.61,8613.3 3037.1,8613.3 CR_IDL_17_12_TerA16.2@3086.06,8613.3 CR_IDL_17_12_TerA16.2@3088.59,8613.3 ; R1R_IDL_17_12_TerA17.2@3037.1,8710.39 3060.28,8710.39 3066.19,8716.3 CR_IDL_17_12_TerA17.2@3086.06,8716.3 CR_IDL_17_12_TerA17.2@3087.51,8716.3 ; R1R_IDL_17_12_TerA18.2@3037.1,8815.39 3060.28,8815.39 3066.19,8821.3 CR_IDL_17_12_TerA18.2@3086.06,8821.3 CR_IDL_17_12_TerA18.2@3088.74,8821.3 ; R1R_IDL_17_12_TerA19.2@3037.1,8920.39 3060.28,8920.39 3066.19,8926.3 CR_IDL_17_12_TerA19.2@3086.06,8926.3 ; R1R_IDL_17_12_TerA21.2@3037.1,9130.39 3079.49,9130.39 CR_IDL_17_12_TerA21.2@3080.64,9131.54 ; R1R_IDL_17_12_TerA22.2@3037.1,9235.39 3078.25,9235.39 CR_IDL_17_12_TerA22.2@3081.09,9238.23 ; R1R_IDL_17_12_TerA23.2@3037.1,9340.39 3060.28,9340.39 3066.19,9346.3 CR_IDL_17_12_TerA23.2@3086.06,9346.3 3108.85,9346.3 3125.28,9362.73 3124.68,9363.33 v1(3124.68,9384.42) ; CR_IDL_17_12_TerA5.2@3072.26,6844.44 CR_IDL_17_12_TerA5.2@3074.72,6844.44 3112.12,6844.44 3122.98,6855.31 v1@3123.7,6856.02 ; CR_IDL_17_12_TerA8.2@3073.72,7159.44 CR_IDL_17_12_TerA8.2@3074.72,7159.44 3080.5,7159.44 3080.5,7160.45 3120.78,7200.73 v1(3128.24,7200.73) ; CR_IDL_17_12_TerA12.2@3075.6,8003.81 CR_IDL_17_12_TerA12.2@3076.75,8002.66 ; CR_IDL_17_12_TerA1.2@3076.46,6417.15 3077.56,6416.05 3077.85,6415.76 v1(3077.85,6372.33) ; CR_IDL_17_12_TerA3.2@3077.17,6632.56 3086.05,6623.68 v1(3112.69,6623.68) ; CR_IDL_17_12_TerA10.2@3078.17,7626.04 3112.86,7660.73 v1(3128.24,7660.73) ; CR_IDL_17_12_TerA2.2@3079.65,6525.38 3091.31,6513.71 v1(3117.74,6513.71) ; CR_IDL_17_12_TerA13.2@3079.65,8103.58 3099.5,8083.73 v1(3119.85,8083.73) ; CR_IDL_17_12_TerA15.2@3080.36,8432.6 3106.29,8432.6 3116.43,8442.73 v1(3133.88,8442.73) ; CR_IDL_17_12_TerA21.2@3080.64,9136.3 CR_IDL_17_12_TerA21.2@3086.06,9136.3 CR_IDL_17_12_TerA21.2@3090.39,9136.3 ; CR_IDL_17_12_TerA22.2@3081.09,9241.3 CR_IDL_17_12_TerA22.2@3086.06,9241.3 CR_IDL_17_12_TerA22.2@3091.08,9241.3 ; CR_IDL_17_12_TerA9.2@3083.69,7422.68 CR_IDL_17_12_TerA9.2@3085.45,7424.44 ; CR_IDL_17_12_TerA17.2@3085.54,8714.33 3086.78,8715.57 CR_IDL_17_12_TerA17.2@3087.51,8716.3 ; CR_IDL_17_12_TerA16.2@3086.09,8615.81 3087.33,8614.57 CR_IDL_17_12_TerA16.2@3088.59,8613.3 ; CR_IDL_17_12_TerA19.2@3086.09,8924.07 3089.26,8920.89 v1(3129.67,8920.89) ; CR_IDL_17_12_TerA21.2@3088.36,9134.27 CR_IDL_17_12_TerA21.2@3090.39,9136.3 ; CR_IDL_17_12_TerA18.2@3088.74,8821.01 3103.19,8806.56 v1(3123,8806.56) ; CR_IDL_17_12_TerA20.2@3089.26,9031.21 3091.99,9028.49 v1(3128.76,9028.49) ; CR_IDL_17_12_TerA22.2@3091.08,9243.23 3103.1,9255.24 3105.12,9253.21 v1(3123.77,9253.21) ; v1(3104.37,7954.88) 3104.37,7975.04 CR_IDL_17_12_TerA12.2@3076.75,8002.66 ; v1(3122.25,9154.35) 3108.43,9154.35 CR_IDL_17_12_TerA21.2@3090.39,9136.3 ; v1(3123.31,8579.04) 3122.86,8579.04 CR_IDL_17_12_TerA16.2@3088.59,8613.3 ; v1(3123.7,6854.59) v1@3123.7,6856.02 ; v1(3128.24,7430.73) 3091.77,7430.73 CR_IDL_17_12_TerA9.2@3085.45,7424.44 ; v1(3130.58,8717.96) 3090.72,8717.96 3089.94,8718.73 CR_IDL_17_12_TerA17.2@3087.51,8716.3 ; v1@3123.7,6856.02 3128.24,6860.56 v1@3123.7,6856.02
  other v1: 53.74,7137.71 1642.33,8258.73 1655.38,9224.73 42.59,9270.73 60.26,9368.29 2489.45,9931.04
12V: 12V.1@2285.76,6285.77 12V.2 12V.3 12V.4 Jtop1.C31 Jtop2.C31 Jtop3.C31 Jtop4.C31 R6.2 | length 8066.4
  Bot Signal w8: R6.2@1059.8,434.92 1059.8,436.23 1059.8,480.19 1088.38,508.77 2928.75,508.77 3049.74,629.76 3049.74,4115.17 2938.84,4226.07 2473.23,4226.07 2386.37,4312.93 2386.37,4386.36 2285.76,4486.96 12V.3@2285.76,6009.79
-3V3: -3V3.1@2285.87,4348.54 -3V3.2 -3V3.3 -3V3.4 JMid1.27 JMid1.28 JMid1.46 JMid1.47 JMid1.65 JMid1.66 JMid1.83 JMid1.84 JMid1.85 JMid2.27 JMid2.28 JMid2.46 JMid2.47 JMid2.65 JMid2.66 JMid2.83 JMid2.84 JMid2.85 JMid3.27 JMid3.28 JMid3.46 JMid3.47 JMid3.65 JMid3.66 JMid3.83 JMid3.84 JMid3.85 JMid4.27 JMid4.28 JMid4.46 JMid4.47 JMid4.65 JMid4.66 JMid4.83 JMid4.84 JMid4.85 R3.2 | length 4909.5
  Top Signal w8: JMid1.83@2793.76,5178.85 2826.54,5178.85 2859.04,5211.35 2896.34,5211.35 2945.97,5260.99 ; 2940.16,5254.97 3010.51,5325.33 3010.51,9946.98 3011.42,9947.89 R3.2@3012.01,9948.47
-5V: -5V.1@1483.08,3476.61 -5V.2 -5V.3 -5V.4 JMid1.30 JMid1.49 JMid1.68 JMid1.87 JMid2.30 JMid2.49 JMid2.68 JMid2.87 JMid3.30 JMid3.49 JMid3.68 JMid3.87 JMid4.30 JMid4.49 JMid4.68 JMid4.87 R1.2 | length 5744.9
  Top Signal w8: R1.2@2708.54,9932.06 2797.81,10021.33 3011.18,10021.33 3053,9979.51 v1(3053,4911.42)
  Mid Signal w8: JMid1.87@2795.35,4862.13 2795.44,4862.21 2843.36,4910.13 3051.71,4910.13 v1(3053,4911.42)
-12V: -12V.1@691.41,6274.77 -12V.2 -12V.3 -12V.4 Jtop1.A31 Jtop2.A31 Jtop3.A31 Jtop4.A31 R4.2 | length 9899.2
  Bot Signal w8: -12V.3@691.41,5998.79 691.41,4430.32 749.15,4372.58 749.15,4273.2 832.02,4190.32 2879.66,4190.32 2984.23,4085.75 2984.23,622.98 2942.07,580.82 826.25,580.82 741.31,495.87 741.31,417.54 R4.2@741.31,417.23
BG0IN_5: Jtop1.B4 Jtop2.B4 Jtop3.B4 Jtop4.B4 | length 2506.2
  Bot Signal w8: Jtop4.B4@388.16,9054.97 433.59,9100.39 1142.86,9100.39 1179.71,9063.54 1188.16,9063.54 1188.28,9063.54 Jtop3.B4@1188.28,9065.36 ; Jtop3.B4@1187.78,9065.36 1188.16,9065.36 Jtop3.B4@1188.28,9065.36 ; Jtop1.B4@2788.16,9054.97 2748.24,9054.97 2705.76,9097.45 2024.34,9097.45 1994.81,9067.92 1994.81,9061.62 Jtop2.B4@1988.16,9054.97 1948.24,9054.97 1905.76,9097.45 1270.57,9097.45 1238.48,9065.36 Jtop3.B4@1188.28,9065.36
BG0OUT_5: Jtop1.B5 Jtop2.B5 Jtop3.B5 Jtop4.B5 | length 2506.4
  Bot Signal w8: Jtop4.B5@388.16,8954.97 428.09,8954.97 470.57,8997.45 1148.99,8997.45 1189.82,8956.62 Jtop3.B5@1190.31,8956.13 ; Jtop3.B5@1188.16,8954.97 1228.09,8954.97 1270.57,8997.44 1870.56,8997.44 1938.28,8997.45 Jtop2.B5@1984.35,8951.38 ; Jtop2.B5@1988.16,8954.97 2028.09,8954.97 2070.57,8997.45 2744.23,8997.45 2787.44,8954.24 2787.92,8953.76 Jtop1.B5@2788.16,8954.97
BG1IN_5: Jtop1.B6 Jtop2.B6 Jtop3.B6 Jtop4.B6 | length 2532.1
  Bot Signal w8: Jtop4.B6@388.16,8854.97 385.95,8850.63 389.22,8853.91 436.72,8901.4 1136.37,8901.4 1182.8,8854.97 Jtop3.B6@1188.16,8854.97 ; Jtop3.B6@1187.13,8853.81 Jtop3.B6@1188.16,8854.97 1230.77,8897.45 1905.76,8897.45 1948.24,8854.97 Jtop2.B6@1987.89,8854.97 ; Jtop2.B6@1980.39,8847.46 Jtop2.B6@1987.89,8854.97 ; Jtop2.B6@1988.16,8854.97 Jtop2.B6@1987.89,8854.97 ; Jtop1.B6@2788.16,8854.97 2745.4,8897.73 2725.6,8897.73 2723.52,8899.81 2032.74,8899.81 1988.03,8855.1 Jtop2.B6@1987.89,8854.97
BG1OUT_5: Jtop1.B7 Jtop2.B7 Jtop3.B7 Jtop4.B7 | length 2528.7
  Bot Signal w8: Jtop4.B7@387.42,8754.26 388.14,8754.98 434.8,8801.64 1142.86,8801.64 1188.16,8756.34 Jtop3.B7@1188.16,8754.97 1228.08,8754.97 1270.57,8797.45 1905.76,8797.45 1911.58,8791.62 1946.59,8791.62 1974.77,8763.44 1974.77,8758.73 1984.4,8758.73 Jtop2.B7@1988.16,8754.97 1994.06,8754.97 2038.32,8799.23 2759.95,8799.23 2793.22,8765.96 2793.22,8760.02 Jtop1.B7@2788.16,8754.97
BG2IN_5: Jtop1.B8 Jtop2.B8 Jtop3.B8 Jtop4.B8 | length 2553.4
  Bot Signal w8: Jtop4.B8@388.16,8654.97 405.26,8654.97 453.22,8702.93 1148.13,8702.93 1184.98,8666.08 1184.98,8661.73 1172.28,8661.73 1172.28,8654.96 Jtop3.B8@1188.16,8654.96 1190.39,8652.74 1197.84,8652.74 1242.54,8697.45 1905.76,8697.45 1948.24,8654.97 Jtop2.B8@1988.16,8654.97 2028.08,8654.97 2070.57,8697.45 2705.76,8697.45 2743.73,8659.48 Jtop1.B8@2788.16,8659.48 ; Jtop1.B8@2788.16,8654.97 Jtop1.B8@2788.16,8659.48 ; Jtop1.B8@2795.01,8659.48 Jtop1.B8@2788.16,8659.48
BG2OUT_5: Jtop1.B9 Jtop2.B9 Jtop3.B9 Jtop4.B9 | length 2522.1
  Bot Signal w8: Jtop4.B9@388.16,8554.97 428.09,8554.97 470.57,8597.45 1149.99,8597.45 1190.32,8557.12 Jtop3.B9@1192.47,8554.97 ; Jtop3.B9@1188.16,8554.97 Jtop3.B9@1192.47,8554.97 ; Jtop3.B9@1193.48,8553.96 Jtop3.B9@1192.47,8554.97 ; Jtop1.B9@2788.16,8554.97 2789.5,8557.92 2787.35,8555.77 2786.55,8554.97 2748.24,8554.97 2705.76,8597.45 2070.57,8597.45 2028.09,8554.97 Jtop2.B9@1988.16,8554.97 1988.32,8551.58 1986.54,8553.35 1942.45,8597.44 1270.57,8597.44 1228.09,8554.97 Jtop3.B9@1192.47,8554.97
BG3IN_5: Jtop1.B10 Jtop2.B10 Jtop3.B10 Jtop4.B10 | length 2558.8
  Bot Signal w8: Jtop4.B10@388.16,8454.97 416.33,8454.97 466.58,8505.22 1150.01,8505.22 1194.21,8461.02 1195.72,8459.51 Jtop3.B10@1198.25,8459.51 ; Jtop3.B10@1191.47,8452.73 Jtop3.B10@1198.25,8459.51 ; Jtop1.B10@2788.16,8454.97 2788.16,8461.08 2792.4,8461.08 2766.3,8487.19 2716.01,8487.19 2705.76,8497.45 2070.57,8497.45 2028.08,8454.97 Jtop2.B10@1988.16,8454.97 1948.24,8454.97 1895.98,8507.22 1616.45,8507.22 1591.3,8532.37 1562.3,8532.37 1537.14,8507.22 1245.95,8507.22 Jtop3.B10@1198.25,8459.51
BG3OUT_5: Jtop1.B11 Jtop2.B11 Jtop3.B11 Jtop4.B11 | length 2542.4
  Bot Signal w8: Jtop4.B11@388.16,8354.97 391.6,8354.97 442.91,8406.28 1143.12,8406.28 1191.3,8358.1 1192.03,8357.37 Jtop3.B11@1188.16,8354.97 1197.95,8354.97 1248.16,8405.17 1934.51,8405.17 1982.82,8356.86 1982.82,8354.97 Jtop2.B11@1988.16,8354.97 1988.39,8356.67 2044.21,8412.48 2726.93,8412.48 2786.19,8353.22 Jtop1.B11@2788.16,8354.97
